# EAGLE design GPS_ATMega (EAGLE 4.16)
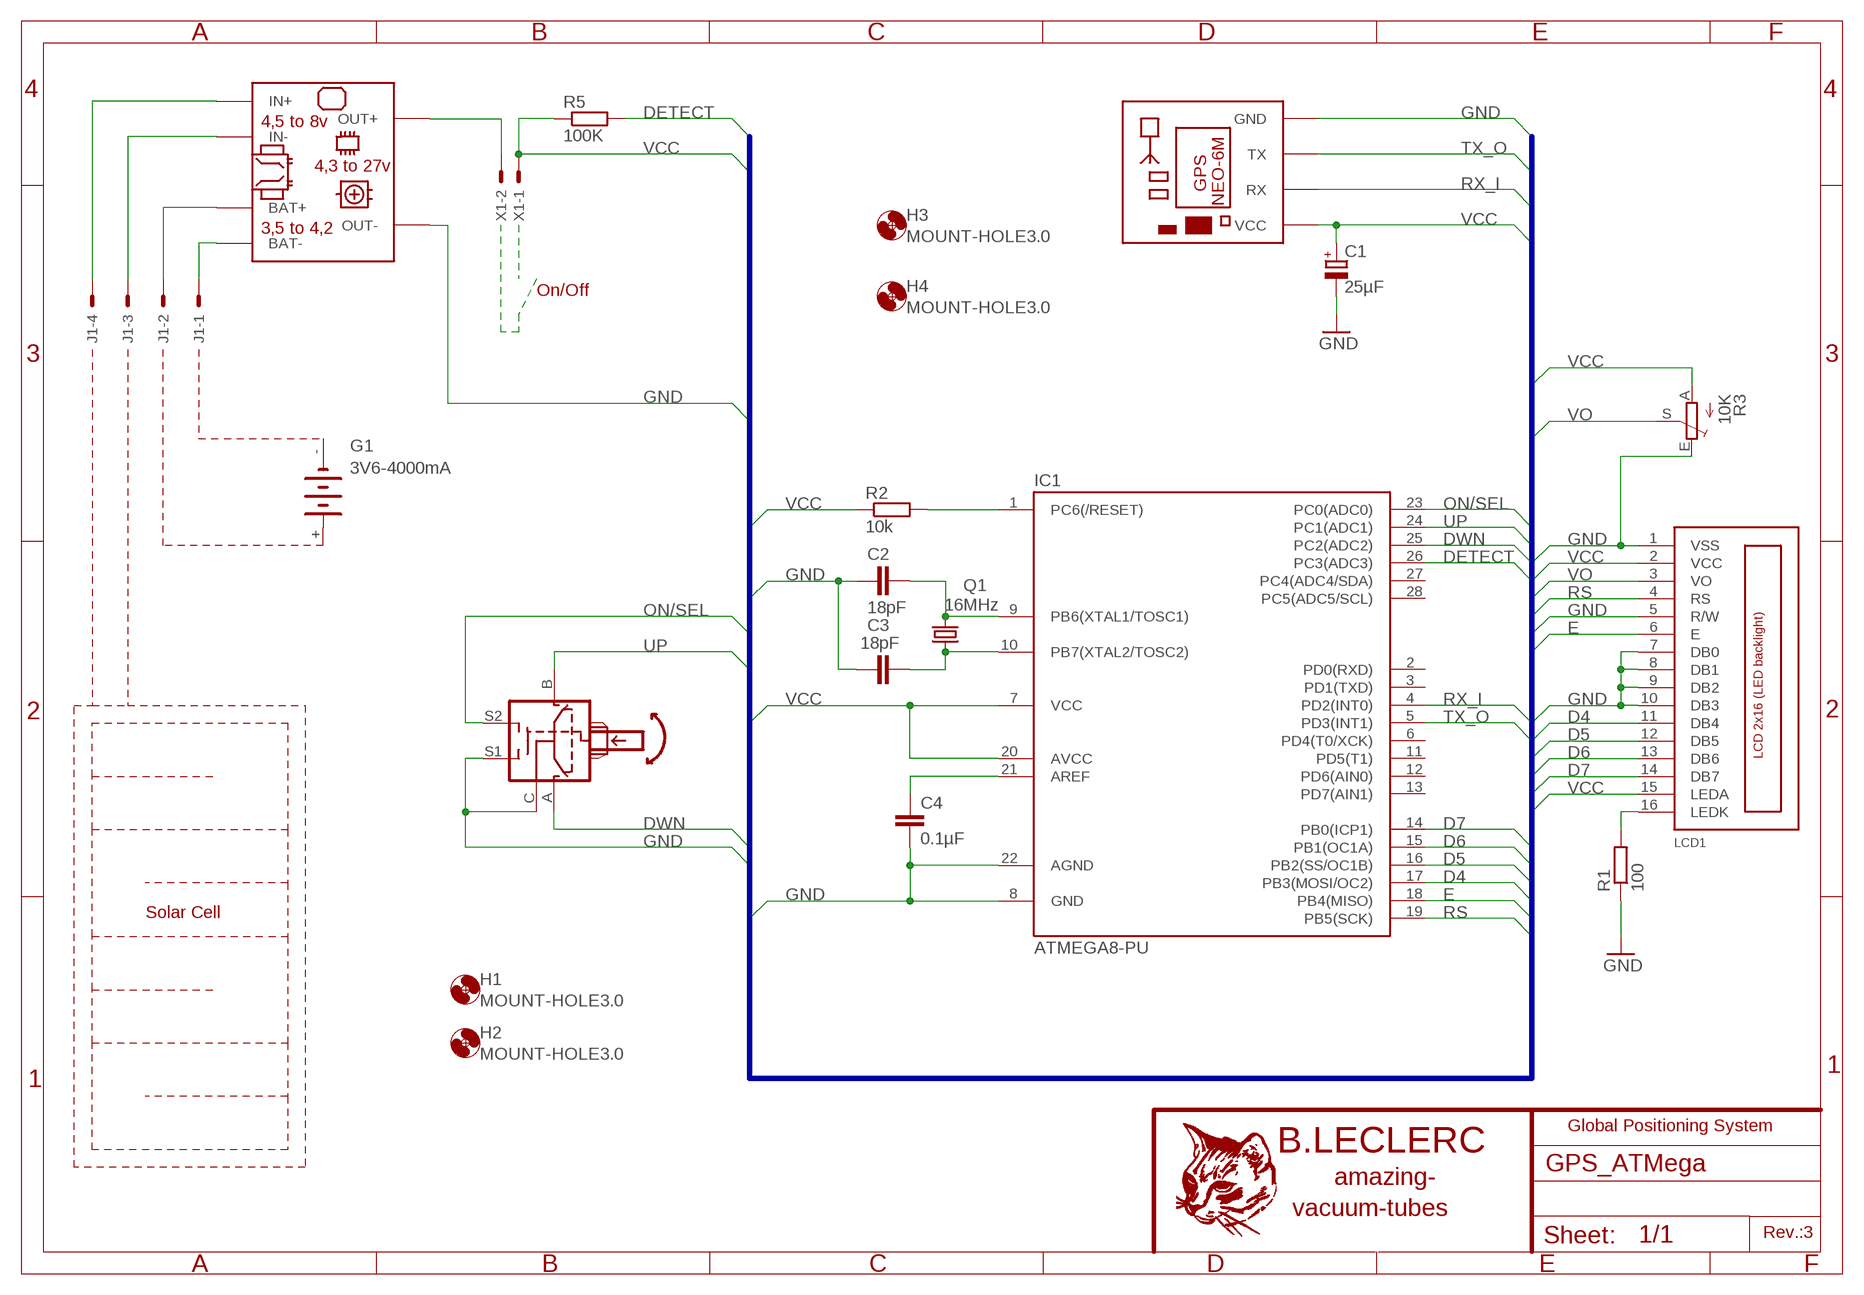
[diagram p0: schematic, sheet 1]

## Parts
C1  25µF  CPOL-EUE2.5-5  [E2,5-5]
C2  18pF  C-EU050-030X075  [C050-030X075]
C3  18pF  C-EU050-030X075  [C050-030X075]
C4  0.1µF  C-EU075-032X103  [C075-032X103]
G1  3V6-4000mA  3V11R  [3V11R]
H1  MOUNT-HOLE3.0  [3,0]
H2  MOUNT-HOLE3.0  [3,0]
H3  MOUNT-HOLE3.0  [3,0]
H4  MOUNT-HOLE3.0  [3,0]
IC1  ATMEGA8-PU  [DIL28-3]
J1  22-27-2041-04  [6410-04]
LCD1  LCD_2X16_SIL  [HY-1602F]
Q1  16MHz  CRYTALHC49S  [HC49/S]
R1  100  R-EU_0207/10  [0207/10]
R2  10k  R-EU_0207/12  [0207/12]
R3  10K  TRIM_EU-LI10  [LI10]
R5  100K  R-EU_0207/12  [0207/12]
SW1  IMPULS_SWITCH  [IMPULS_SWITCH]
U$2  LITHIUM_BAT_BOOST  [LITHIUM_BAT_BOOST]
U$5  GY-NEO6MV2  [GY-NEO6MV2]
X1  22-23-2021  [22-23-2021]

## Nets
D4: IC1.17(PB3(MOSI/OC2)) LCD1.11(DB4)
D5: IC1.16(PB2(SS/OC1B)) LCD1.12(DB5)
D6: IC1.15(PB1(OC1A)) LCD1.13(DB6)
D7: IC1.14(PB0(ICP1)) LCD1.14(DB7)
DETECT: IC1.26(PC3(ADC3)) R5.2
DWN: IC1.25(PC2(ADC2)) SW1.A
E: IC1.18(PB4(MISO)) LCD1.6(E)
GND: C1.- C2.1 C3.1 C4.2 IC1.8(GND) IC1.22(AGND) LCD1.1(VSS) LCD1.5(R/W) LCD1.7(DB0) LCD1.8(DB1) LCD1.9(DB2) LCD1.10(DB3) R1.1 R3.E SW1.C SW1.S1 U$2.OUT- U$5.GND
N$1: J1.4 U$2.IN+
N$4: U$2.OUT+ X1.2
N$5: J1.3 U$2.IN-
N$6: LCD1.16(LEDK) R1.2
N$7: J1.1 U$2.BAT-
N$8: J1.2 U$2.BAT+
N$9: IC1.1(PC6(/RESET)) R2.2
N$11: C2.2 IC1.9(PB6(XTAL1/TOSC1)) Q1.2
N$12: C3.2 IC1.10(PB7(XTAL2/TOSC2)) Q1.1
N$13: C4.1 IC1.21(AREF)
ON/SEL: IC1.23(PC0(ADC0)) SW1.S2
RS: IC1.19(PB5(SCK)) LCD1.4(RS)
RX_I: IC1.4(PD2(INT0)) U$5.RX
TX_O: IC1.5(PD3(INT1)) U$5.TX
UP: IC1.24(PC1(ADC1)) SW1.B
VCC: C1.+ IC1.7(VCC) IC1.20(AVCC) LCD1.2(VCC) LCD1.15(LEDA) R2.1 R3.A R5.1 U$5.VCC X1.1
VO: LCD1.3(VO) R3.S
Unconnected: G1.+ G1.- IC1.2(PD0(RXD)) IC1.3(PD1(TXD)) IC1.6(PD4(T0/XCK)) IC1.11(PD5(T1)) IC1.12(PD6(AIN0)) IC1.13(PD7(AIN1)) IC1.27(PC4(ADC4/SDA)) IC1.28(PC5(ADC5/SCL))

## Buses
B$1

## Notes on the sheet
- On/Off
- Solar Cell
- Global Positioning System
- Rev.:3

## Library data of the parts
C1 = rcl:CPOL-EU: POLARIZED CAPACITOR, European symbol
C2-C4 = rcl:C-EU: CAPACITOR, European symbol
G1 = battery:3V11R: NC ACCU Varta
H1-H4 = holes:MOUNT-HOLE: MOUNTING HOLE with drill center marker
IC1 = atmega8:ATMEGA8-PU
J1 = con-molex:22-?-04: CONNECTOR wire to board 2.54 mm (.1 inch) pitch header
LCD1 = lcd_2x16_led_backlight:LCD_2X16_SIL
Q1 = crystal:CRYTAL: CRYSTAL
R1 R2 R5 = rcl:R-EU_: RESISTOR, European symbol
R3 = pot:TRIM_EU-: POTENTIOMETER
SW1 = switch:IMPULS_SWITCH
U$2 = Arduino:LITHIUM_BAT_BOOST
U$5 = Arduino:GY-NEO6MV2
X1 = con-molex:22-23-2021: .100" (2.54mm) Center Header - 2 Pin

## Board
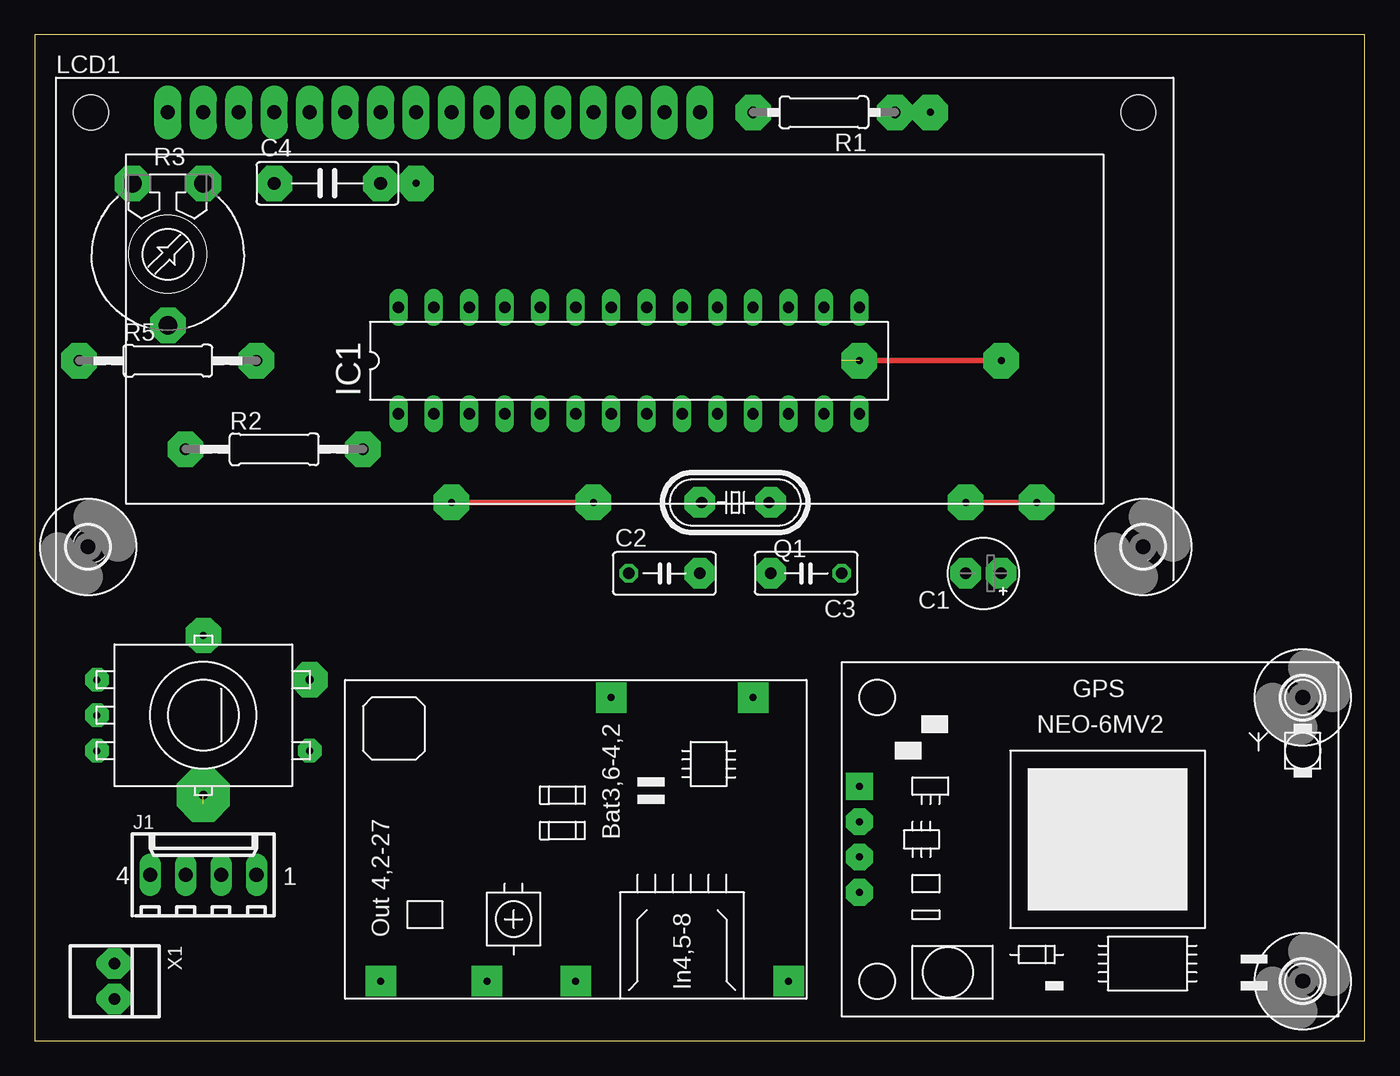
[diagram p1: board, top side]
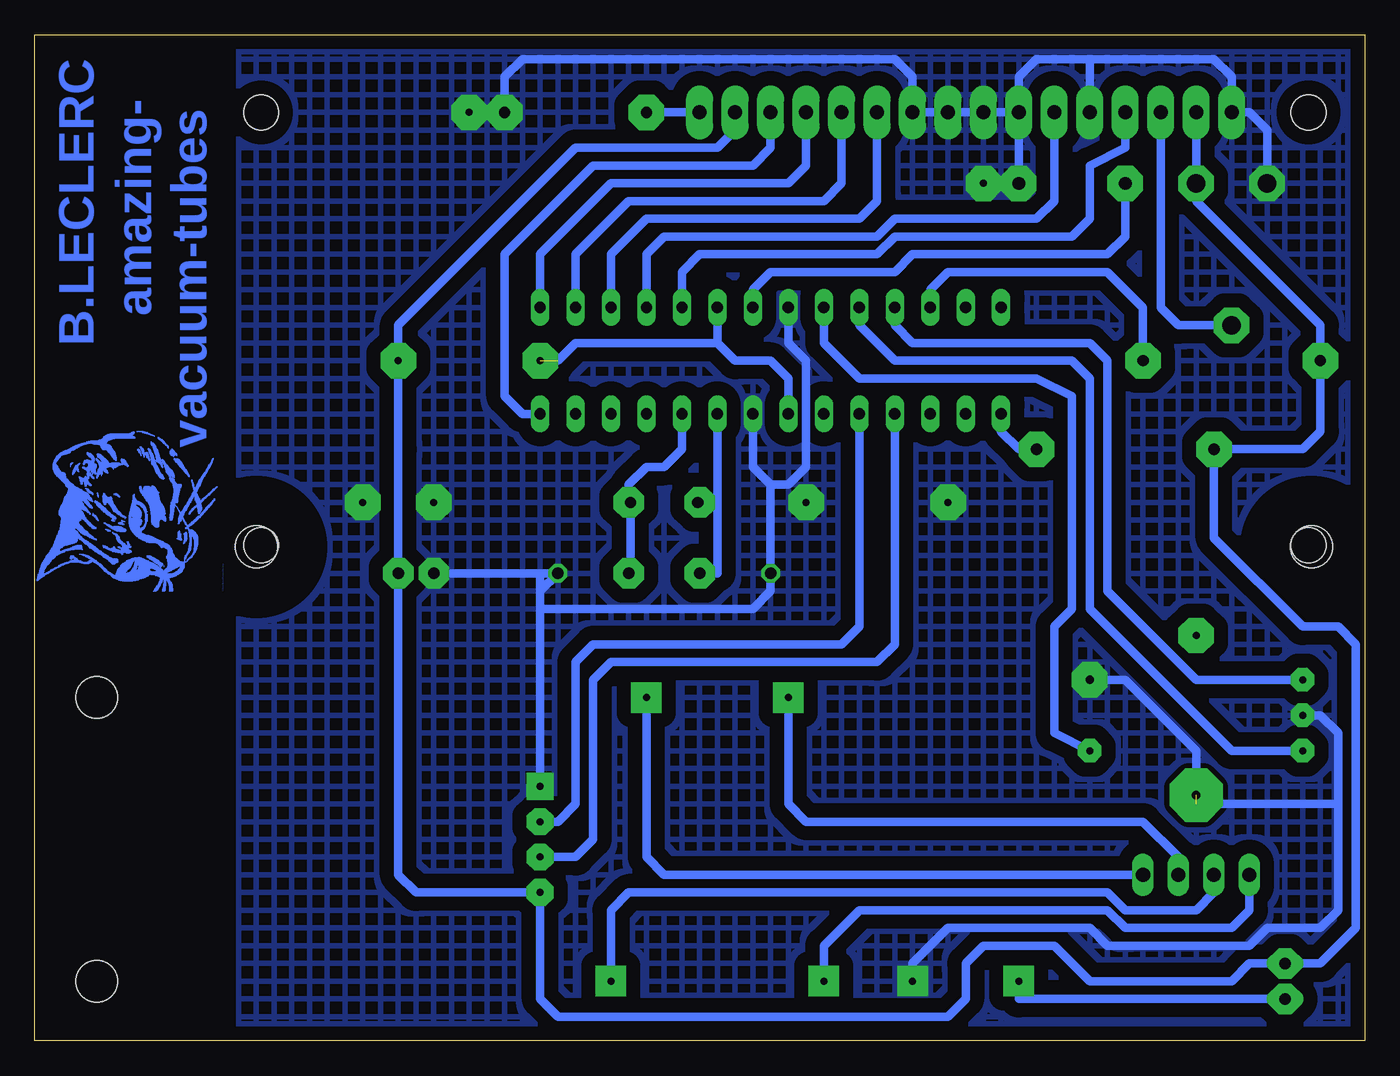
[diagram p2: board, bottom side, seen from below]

Size 95.23 x 72.06 mm. Coordinates in mm from the lower left corner, seen from the top.
Outline: 0,0 95.23,0 95.23,72.06 0,72.06 0,0
Copper layers (1*16): Top 0.035mm / dielectric 1.5mm / Bottom 0.035mm
Design rules "default": minimum track width 10mil, minimum drill 24mil, track to track 8mil, track to pad 8mil, pad to pad 8mil, via to via 8mil, smd to smd 8mil, copper to edge 40mil, drill to drill 8mil, minimum pad ring 10mil, minimum via ring 8mil, stop-mask expansion 4mil, vias tented up to drill 0mil, thermal gap 10mil

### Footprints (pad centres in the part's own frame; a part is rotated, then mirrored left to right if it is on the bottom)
E2,5-5 = drill 0.813 pad 1.6 round: + -1.27,0 | drill 0.813 pad 1.6 octagon: - 1.27,0
C050-030X075 = drill 0.813 octagon: 1 -2.54,0; 2 2.54,0
C075-032X103 = drill 0.914 octagon: 1 -3.81,0; 2 3.81,0
3V11R = drill 1.118 pad 2.54 octagon: + -5.08,0; - 5.08,0
3,0 = hole 3: 0,0
DIL28-3 = drill 0.813 long: 1 -16.51,-3.81; 2 -13.97,-3.81; 3 -11.43,-3.81; 4 -8.89,-3.81; 5 -6.35,-3.81; 6 -3.81,-3.81; 7 -1.27,-3.81; 8 1.27,-3.81; 9 3.81,-3.81; 10 6.35,-3.81; 11 8.89,-3.81; 12 11.43,-3.81; 13 13.97,-3.81; 14 16.51,-3.81; 15 16.51,3.81; 16 13.97,3.81; 17 11.43,3.81; 18 8.89,3.81; 19 6.35,3.81; 20 3.81,3.81; 21 1.27,3.81; 22 -1.27,3.81; 23 -3.81,3.81; 24 -6.35,3.81; 25 -8.89,3.81; 26 -11.43,3.81; 27 -13.97,3.81; 28 -16.51,3.81
6410-04 = drill 1.016 long: 1 3.81,0; 2 1.27,0; 3 -1.27,0; 4 -3.81,0
HY-1602F = drill 1 pad 1.93 long: 1 2.54,0; 2 5.08,0; 3 7.62,0; 4 10.16,0; 5 12.7,0; 6 15.24,0; 7 17.78,0; 8 20.32,0; 9 22.86,0; 10 25.4,0; 11 27.94,0; 12 30.48,0; 13 33.02,0; 14 35.56,0; 15 38.1,0; 16 40.64,0 | hole 2.5: -2.96,0; 72.04,0; -2.96,-31; 72.04,-31
HC49/S = drill 0.813 round: 1 -2.413,0; 2 2.413,0
0207/10 = drill 0.813 octagon: 1 -5.08,0; 2 5.08,0
0207/12 = drill 0.813 octagon: 1 -6.35,0; 2 6.35,0
LI10 = drill 1.321 octagon: A -2.54,-5.08; E 2.54,-5.08; S 0,5.08
IMPULS_SWITCH = drill 0.5 pad 1.676 octagon: A -7.62,2.54; B -7.62,-2.54; C -7.62,0; S1 7.62,2.54; S2 7.62,-2.54 | drill 0.5 pad 2.54 octagon: P$1 0,5.715; P$2 0,-5.715
LITHIUM_BAT_BOOST = drill 0.5 pad 2.184 square: BAT+ 20.32,12.7; BAT- 20.32,2.54; IN+ 0,15.24; IN- 0,0; OUT+ 0,29.21; OUT- 0,21.59
GY-NEO6MV2 = drill 0.5 pad 1.93 square: GND 1.27,3.81 | drill 0.5 pad 1.93 octagon: RX 1.27,-1.27; TX 1.27,1.27; VCC 1.27,-3.81
22-23-2021 = drill 0.813 long: 1 -1.27,0; 2 1.27,0

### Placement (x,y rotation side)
C1  67.94,33.49 180 top
C2  45.08,33.49 0 top
C3  55.24,33.49 180 top
C4  20.95,61.43 0 top
G1  not placed on the board
H1  90.8,24.6 0 top
H2  90.8,4.28 0 top
H3  79.37,35.39 0 top
H4  3.8,35.39 0 top
IC1  42.54,48.73 0 top
J1  12.06,11.9 0 top
LCD1  6.98,66.51 0 top
Q1  50.16,38.57 180 top
R1  56.51,66.51 180 top
R2  17.14,42.38 0 top
R3  9.52,56.35 180 top
R5  9.52,48.73 0 top
SW1  12.06,23.33 0 top
U$2  53.97,4.28 90 top
U$3  [CHAT1]  81.91,32.22 90 bottom
U$5  57.78,14.44 0 top
X1  5.71,4.28 270 top

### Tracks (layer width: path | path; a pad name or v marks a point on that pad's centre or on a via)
D4
  Bottom 0.61: LCD1.11 34.92,60.16 36.19,58.89 51.43,58.89 53.97,56.35 IC1.17
D5
  Bottom 0.61: LCD1.12 37.46,61.43 38.73,60.16 52.7,60.16 56.51,56.35 IC1.16
D6
  Bottom 0.61: LCD1.13 40,62.7 41.27,61.43 53.97,61.43 59.05,56.35 IC1.15
D7
  Bottom 0.61: LCD1.14 42.54,63.97 43.81,62.7 55.24,62.7 61.59,56.35 61.59,46.19 60.32,44.92 IC1.14
DETECT
  Bottom 0.61: IC1.26 31.11,53.81 29.84,55.08 18.41,55.08 15.87,52.54 R5.2
DWN
  Bottom 0.61: IC1.25 33.65,51.27 32.38,50 19.68,50 18.41,48.73 18.41,32.22 12.06,25.87 SW1.A
E
  Bottom 0.61: LCD1.6 22.22,60.16 23.49,58.89 33.65,58.89 34.92,57.62 50.16,57.62 51.43,56.35 IC1.18
GND  (via drill 0.5 pad 1.27, 0.5 pad 2.18, 0.5 pad 2.54, 0.6 pad 2.54, 0.6 pad 3.81)  (1 unrouted)
  Top 0.406: v66.67,38.57 v71.75,38.57 | v29.84,38.57 v40,38.57
  Bottom 0.61: R3.E 6.98,65.24 8.25,66.51 LCD1.1 9.52,69.05 10.79,70.32 19.68,70.32 | 19.68,70.32 23.49,70.32 24.76,69.05 LCD1.7 | 19.68,70.32 LCD1.5 | LCD1.7 C4.2 | LCD1.7 LCD1.8 LCD1.9 | LCD1.9 LCD1.10 | LCD1.9 LCD1.10 | IC1.8 43.81,41.11 42.54,39.84 | 42.54,39.84 C2.1 42.54,32.22 43.81,30.95 59.05,30.95 | 59.05,32.22 C3.1 59.05,33.49 | 59.05,33.49 C1.- | U$2.OUT- 32.38,5.55 29.84,8.09 19.68,8.09 18.41,6.82 8.25,6.82 6.98,8.09 3.17,8.09 1.9,9.36 1.9,16.98 | 1.9,16.98 1.9,22.06 3.17,23.33 SW1.C | 1.9,16.98 12.06,16.98 12.06,20.79 17.14,25.87 SW1.S1 | IC1.22 41.27,50 40,48.73 40,41.11 41.27,39.84 42.54,39.84 | LCD1.10 32.38,69.05 33.65,70.32 60.32,70.32 61.59,69.05 R1.1 | 59.05,32.22 59.05,33.49 | 59.05,30.95 59.05,32.22 | 59.05,30.95 U$5.GND
  other vias: 6.98,61.43 24.76,61.43 61.59,66.51 66.67,33.49 9.52,66.51 19.68,66.51 24.76,66.51 27.3,66.51 29.84,66.51 32.38,66.51 41.27,52.54 43.81,44.92 27.3,61.43 64.13,66.51 12.06,17.61 19.68,25.87
  pour Bottom (isolate 1.016, no thermals, hatched): 0.63,71.59 80.64,71.59 80.64,0.47 0.63,0.47
N$1
  Bottom 0.61: U$2.IN+ 38.73,6.82 36.19,9.36 18.41,9.36 17.14,8.09 9.52,8.09 8.25,9.36 J1.4
N$4
  Bottom 0.61: X1.2 24.76,3.01 U$2.OUT+
N$5
  Bottom 0.61: J1.3 10.79,10.63 12.06,9.36 17.14,9.36 18.41,10.63 52.7,10.63 53.97,9.36 U$2.IN-
N$6
  Bottom 0.61: LCD1.16 R1.2
N$7
  Bottom 0.61: J1.1 50.16,11.9 51.43,13.17 U$2.BAT-
N$8
  Bottom 0.61: J1.2 13.33,13.17 15.87,15.71 40,15.71 41.27,16.98 U$2.BAT+
N$9
  Bottom 0.61: IC1.1 26.03,43.65 24.76,42.38 R2.2
N$11
  Bottom 0.61: 46.35,38.57 IC1.9 | 46.35,38.57 Q1.2 | 46.35,38.57 46.35,33.49 C2.2
N$12
  Bottom 0.61: IC1.10 48.89,42.38 50.16,41.11 51.43,41.11 52.7,39.84 52.7,38.57 Q1.1 52.57,33.62 C3.2
N$13
  Bottom 0.61: C4.1 17.14,57.62 18.41,56.35 32.38,56.35 33.65,55.08 42.54,55.08 43.81,53.81 IC1.21
N$14  (via drill 0.5 pad 2.54)
  other vias: 51.43,66.51
N$15  (via drill 0.5 pad 1.27)
  other vias: 5.71,5.55
N$16  (via drill 0.5 pad 1.27)
  other vias: 5.71,3.01
N$17  (via drill 0.5 pad 2.54)
  other vias: 17.14,61.43
N$18  (via drill 0.5 pad 1.27)
  other vias: 15.87,11.9
N$19  (via drill 0.5 pad 2.54)
  other vias: 12.06,61.43
N$20  (via drill 0.5 pad 2.54)
  other vias: 9.52,51.27
N$21  (via drill 0.5 pad 2.54)
  other vias: 3.17,48.73
N$22  (via drill 0.5 pad 2.54)
  other vias: 15.87,48.73
N$23  (via drill 0.5 pad 2.54)
  other vias: 23.49,42.38
N$24  (via drill 0.5 pad 2.54)
  other vias: 10.79,42.38
N$25  (via drill 0.5 pad 1.27)
  other vias: 13.33,11.9
N$26  (via drill 0.5 pad 1.27)
  other vias: 10.79,11.9
N$27  (via drill 0.5 pad 1.27)
  other vias: 8.25,11.9
N$28  (via drill 0.5 pad 1.27)
  other vias: 14.6,66.51
N$29  (via drill 0.5 pad 1.27)
  other vias: 12.06,66.51
N$30  (via drill 0.5 pad 2.18)
  other vias: 69.21,33.49
N$31  (via drill 0.5 pad 2.18)
  other vias: 47.62,38.57
N$32  (via drill 0.5 pad 2.18)
  other vias: 52.7,38.57
N$33  (via drill 0.5 pad 2.18)
  other vias: 47.62,33.49
N$34  (via drill 0.5 pad 2.18)
  other vias: 52.7,33.49
N$35  (via drill 0.5 pad 1.27)
  other vias: 28.57,52.54
N$36  (via drill 0.5 pad 1.27)
  other vias: 17.14,66.51
N$37  (via drill 0.5 pad 1.27)
  other vias: 38.73,52.54
N$38  (via drill 0.5 pad 1.27)
  other vias: 22.22,66.51
N$39  (via drill 0.5 pad 1.27)
  other vias: 36.19,52.54
N$40  (via drill 0.5 pad 1.27)
  other vias: 31.11,52.54
N$41  (via drill 0.5 pad 1.27)
  other vias: 46.35,52.54
N$42  (via drill 0.5 pad 1.27)
  other vias: 43.81,52.54
N$43  (via drill 0.5 pad 1.27)
  other vias: 34.92,66.51
N$44  (via drill 0.5 pad 1.27)
  other vias: 37.46,66.51
N$45  (via drill 0.5 pad 1.27)
  other vias: 47.62,66.51
N$46  (via drill 0.5 pad 1.27)
  other vias: 45.08,66.51
N$47  (via drill 0.5 pad 1.27)
  other vias: 42.54,66.51
N$48  (via drill 0.5 pad 1.27)
  other vias: 40,66.51
N$49  (via drill 0.5 pad 1.27)
  other vias: 28.57,44.92
N$50  (via drill 0.5 pad 1.27)
  other vias: 59.05,44.92
N$51  (via drill 0.5 pad 1.27)
  other vias: 56.51,44.92
N$52  (via drill 0.5 pad 1.27)
  other vias: 38.73,44.92
N$53  (via drill 0.5 pad 1.27)
  other vias: 59.05,52.54
N$54  (via drill 0.5 pad 1.27)
  other vias: 51.43,44.92
N$55  (via drill 0.5 pad 1.27)
  other vias: 51.43,52.54
N$56  (via drill 0.5 pad 2.18)
  other vias: 5.71,5.55
N$57  (via drill 0.5 pad 1.27)
  other vias: 26.03,52.54
N$58  (via drill 0.5 pad 1.27)
  other vias: 33.65,52.54
N$59  (via drill 0.5 pad 1.27)
  other vias: 48.89,52.54
N$60  (via drill 0.5 pad 1.27)
  other vias: 53.97,52.54
N$61  (via drill 0.5 pad 1.27)
  other vias: 56.51,52.54
N$62  (via drill 0.5 pad 1.27)
  other vias: 53.97,44.92
N$63  (via drill 0.5 pad 1.27)
  other vias: 48.89,44.92
N$64  (via drill 0.5 pad 1.27)
  other vias: 46.35,44.92
N$65  (via drill 0.5 pad 2.18)
  other vias: 5.71,3.01
N$66  (via drill 0.5 pad 1.27)
  other vias: 36.19,44.92
N$67  (via drill 0.5 pad 1.27)
  other vias: 33.65,44.92
N$68  (via drill 0.5 pad 1.27)
  other vias: 31.11,44.92
N$69  (via drill 0.5 pad 1.27)
  other vias: 26.03,44.92
N$70  (via drill 0.5 pad 1.27)
  other vias: 41.27,44.92
ON/SEL
  Bottom 0.61: IC1.23 38.73,50 36.19,47.46 23.49,47.46 20.95,46.19 20.95,30.95 22.22,29.68 22.22,22.06 SW1.S2
RS
  Bottom 0.61: LCD1.4 17.14,63.97 19.68,62.7 19.68,58.89 20.95,57.62 33.65,57.62 34.92,56.35 47.62,56.35 48.89,55.08 IC1.19
RX_I
  Bottom 0.61: IC1.4 33.65,28.41 34.92,27.14 53.97,27.14 55.24,25.87 55.24,14.44 56.51,13.17 U$5.RX
TX_O
  Bottom 0.61: IC1.5 36.19,29.68 37.46,28.41 55.24,28.41 56.51,27.14 56.51,16.98 57.78,15.71 U$5.TX
UP
  Bottom 0.61: IC1.24 36.19,51.27 33.65,48.73 20.95,48.73 19.68,47.46 19.68,30.95 9.52,20.79 SW1.B
VCC  (via drill 0.5 pad 2.54)  (1 unrouted)
  Top 0.406: v69.21,48.73 v59.05,48.73
  Bottom 0.61: LCD1.2 R3.A 12.06,60.16 3.17,51.27 R5.1 3.17,43.65 4.44,42.38 R2.1 10.79,36.03 4.44,29.68 1.9,29.68 0.63,28.41 0.63,8.09 3.17,5.55 X1.1 8.25,5.55 9.52,4.28 19.68,4.28 22.22,6.82 27.3,6.82 28.57,5.55 28.57,3.01 29.84,1.74 57.78,1.74 59.05,3.01 U$5.VCC 67.94,10.63 69.21,11.9 C1.+ 69.21,42.38 v69.21,48.73 69.21,51.27 56.51,63.97 46.35,63.97 45.08,65.24 LCD1.15 | 46.35,50 45.08,48.73 42.54,48.73 41.27,47.46 IC1.7 | 46.35,50 IC1.20 | 46.35,50 56.51,50 57.78,48.73
VO
  Bottom 0.61: R3.S 13.33,51.27 14.6,52.54 LCD1.3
